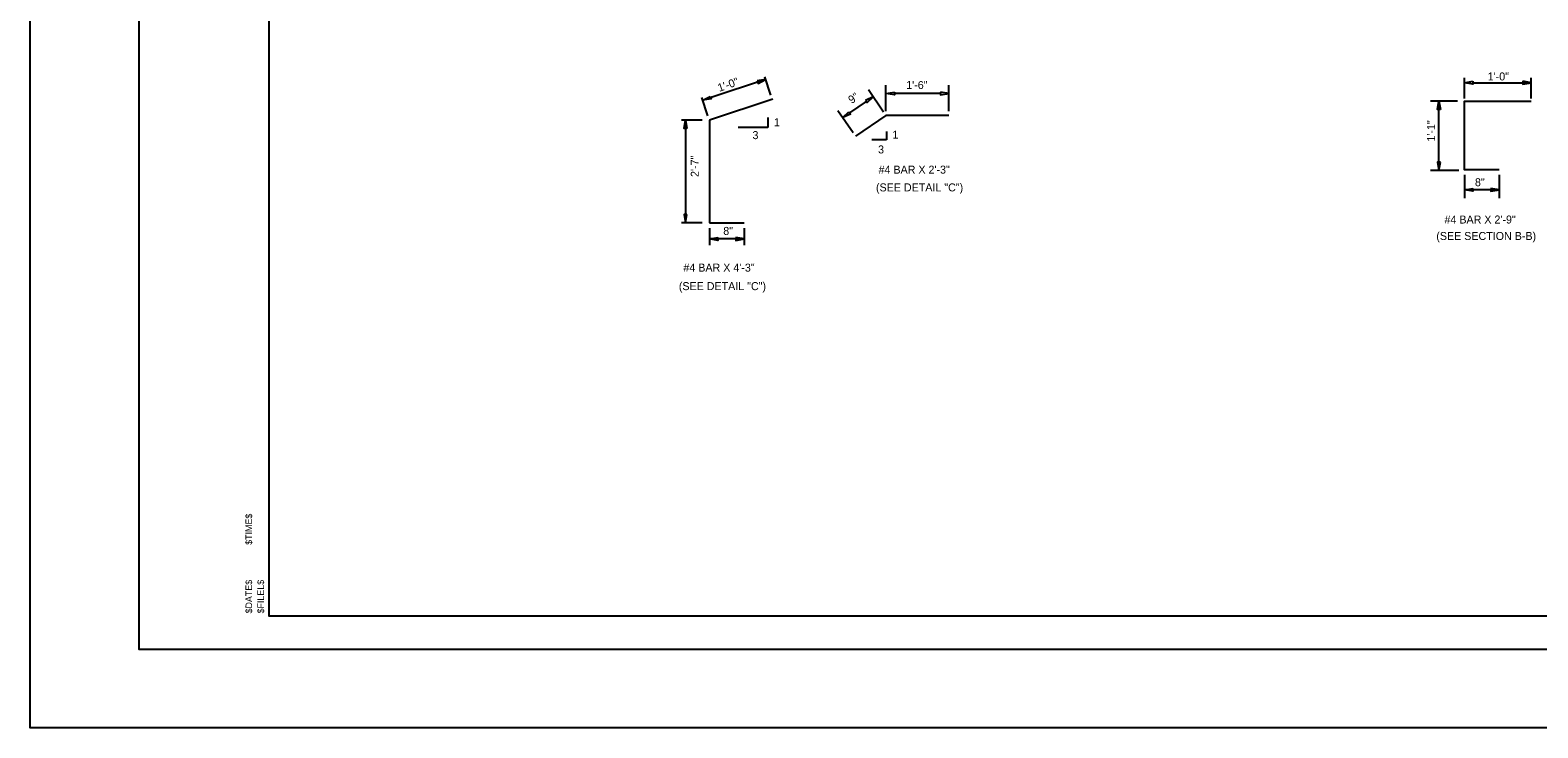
# Model space of a CAD drawing. Extents: x 570 to 2152770, y 726 to 139926.
# Drawn here: x 2152510.48 to 2152533.11, y 139374.83 to 139385.3 of the extents above; entities that cross this region are included whole.
import ezdxf

# ---------------------------------------------------------------- set-up
doc = ezdxf.new("R2010")
doc.units = 0
for name, color, linetype in [('4', 7, 'Continuous'), ('PR_Dimensions', 7, 'Continuous'), ('SHT_Plot_Shape_Full', 7, 'Continuous'), ('SHT_Plot_Shape_Half', 7, 'Continuous'), ('SHT_Plot_Stamp', 7, 'Continuous'), ('SHT_Sheet_Border', 7, 'Continuous'), ('SHT_Standard_Sheet_Txt', 7, 'Continuous'), ('T', 7, 'Continuous')]:
    doc.layers.add(name, color=color, linetype=linetype)

# ---------------------------------------------------------------- blocks, each defined once
blk = doc.blocks.new('Stamp_Plot_Stamp')
at = {"layer": 'SHT_Plot_Stamp'}
for s, p in [('$TIME$', (1.695, 1.572)), ('$DATE$', (1.695, 0.542)), ('$FILEL$', (1.873, 0.542))]:
    blk.add_text(s, height=0.1, rotation=90, dxfattribs=at).set_placement(p)

msp = doc.modelspace()

# ---------------------------------------------------------------- linework, layer by layer
at = {"layer": '4'}
for p, q in [((2152521.626, 139384.269), (2152520.673, 139383.951)), ((2152520.673, 139383.951), (2152520.673, 139382.41)), ((2152520.673, 139382.41), (2152521.195, 139382.41))]:
    msp.add_line(p, q, dxfattribs=at)
for points in [[(2152532.527, 139383.205), (2152532.005, 139383.205), (2152532.005, 139384.237), (2152533.009, 139384.237)], [(2152524.266, 139384.023), (2152523.324, 139384.023), (2152522.865, 139383.71)]]:
    msp.add_lwpolyline(points, dxfattribs=at)
at = {"layer": 'PR_Dimensions'}
for p, q in [((2152521.518, 139384.565), (2152520.684, 139384.286)), ((2152521.596, 139384.33), (2152521.505, 139384.602)), ((2152523.324, 139384.086), (2152523.324, 139384.48)), ((2152524.266, 139384.086), (2152524.266, 139384.48)), ((2152532.005, 139384.276), (2152532.005, 139384.587)), ((2152532.13, 139384.515), (2152533.009, 139384.515)), ((2152533.009, 139384.276), (2152533.009, 139384.587)), ((2152520.651, 139384.016), (2152520.56, 139384.291)), ((2152523.289, 139384.075), (2152523.062, 139384.408)), ((2152524.141, 139384.354), (2152523.45, 139384.354)), ((2152522.83, 139383.762), (2152522.603, 139384.095)), ((2152523.029, 139384.233), (2152522.778, 139384.062)), ((2152531.9, 139384.237), (2152531.499, 139384.237)), ((2152531.624, 139383.247), (2152531.624, 139384.203)), ((2152520.566, 139383.951), (2152520.257, 139383.951)), ((2152520.314, 139383.951), (2152520.314, 139382.452)), ((2152521.552, 139383.842), (2152521.104, 139383.842)), ((2152521.552, 139383.991), (2152521.552, 139383.842)), ((2152523.33, 139383.656), (2152523.111, 139383.656)), ((2152523.33, 139383.782), (2152523.33, 139383.656)), ((2152531.923, 139383.196), (2152531.499, 139383.196)), ((2152532.005, 139383.132), (2152532.005, 139382.781)), ((2152532.527, 139383.132), (2152532.527, 139382.781)), ((2152532.527, 139382.907), (2152532.005, 139382.907)), ((2152520.566, 139382.41), (2152520.257, 139382.41)), ((2152520.673, 139382.331), (2152520.673, 139382.077)), ((2152521.195, 139382.331), (2152521.195, 139382.077)), ((2152521.195, 139382.169), (2152520.673, 139382.169))]:
    msp.add_line(p, q, dxfattribs=at)
for points in [[(2152521.392, 139384.545), (2152521.405, 139384.505), (2152521.518, 139384.565)], [(2152532.13, 139384.536), (2152532.13, 139384.495), (2152532.005, 139384.515)], [(2152532.884, 139384.536), (2152532.884, 139384.495), (2152533.009, 139384.515)], [(2152520.686, 139384.31), (2152520.699, 139384.271), (2152520.573, 139384.251)], [(2152523.018, 139384.25), (2152523.041, 139384.216), (2152523.133, 139384.304)], [(2152523.45, 139384.375), (2152523.45, 139384.333), (2152523.324, 139384.354)], [(2152524.141, 139384.375), (2152524.141, 139384.333), (2152524.266, 139384.354)], [(2152522.766, 139384.079), (2152522.79, 139384.044), (2152522.674, 139383.991)], [(2152531.645, 139384.112), (2152531.604, 139384.112), (2152531.624, 139384.237)], [(2152520.335, 139383.826), (2152520.293, 139383.826), (2152520.314, 139383.951)], [(2152531.645, 139383.321), (2152531.604, 139383.321), (2152531.624, 139383.196)], [(2152532.13, 139382.928), (2152532.13, 139382.886), (2152532.005, 139382.907)], [(2152532.401, 139382.928), (2152532.401, 139382.886), (2152532.527, 139382.907)], [(2152520.335, 139382.535), (2152520.293, 139382.535), (2152520.314, 139382.41)], [(2152520.799, 139382.189), (2152520.799, 139382.148), (2152520.673, 139382.169)], [(2152521.07, 139382.189), (2152521.07, 139382.148), (2152521.195, 139382.169)]]:
    msp.add_lwpolyline(points, close=True, dxfattribs=at)
at = {"layer": 'SHT_Plot_Shape_Full'}
msp.add_lwpolyline([(2152510.479, 139398.83), (2152546.479, 139398.83), (2152546.479, 139374.83), (2152510.479, 139374.83)], close=True, dxfattribs=at)
at = {"layer": 'SHT_Plot_Shape_Half'}
msp.add_lwpolyline([(2152512.116, 139398.005), (2152546.116, 139398.005), (2152546.116, 139376.005), (2152512.116, 139376.005)], close=True, dxfattribs=at)
at = {"layer": 'SHT_Sheet_Border'}
msp.add_lwpolyline([(2152545.566, 139376.505), (2152514.066, 139376.505), (2152514.066, 139397.505), (2152545.566, 139397.505)], close=True, dxfattribs=at)

# ---------------------------------------------------------------- block references
at = {"layer": 'SHT_Standard_Sheet_Txt'}
msp.add_blockref('Stamp_Plot_Stamp', (2152512.116, 139376.005), dxfattribs=at)

# ---------------------------------------------------------------- texts
at = {"layer": 'T'}
for s, rotation, p in [('1\'-0"', 19.1967, (2152520.822, 139384.377)), ('9"', 34.2887, (2152522.809, 139384.193)), ('1\'-1"', 90, (2152531.566, 139383.631)), ('2\'-7"', 90, (2152520.514, 139383.1))]:
    msp.add_text(s, height=0.12, rotation=rotation, dxfattribs=at).set_placement(p)
for s, p in [('1\'-6"', (2152523.628, 139384.42)), ('1\'-0"', (2152532.355, 139384.549)), ('1', (2152521.642, 139383.862)), ('3', (2152521.32, 139383.668)), ('3', (2152523.205, 139383.453)), ('1', (2152523.421, 139383.676)), ('#4 BAR X 2\'-3"', (2152523.213, 139383.15)), ('(SEE DETAIL "C")', (2152523.174, 139382.883)), ('8"', (2152532.164, 139382.961)), ('#4 BAR X 2\'-9"', (2152531.707, 139382.401)), ('8"', (2152520.882, 139382.23)), ('(SEE SECTION B-B)', (2152531.584, 139382.154)), ('#4 BAR X 4\'-3"', (2152520.284, 139381.679)), ('(SEE DETAIL "C")', (2152520.215, 139381.401))]:
    msp.add_text(s, height=0.12, dxfattribs=at).set_placement(p)

doc.saveas('drawing.dxf')
